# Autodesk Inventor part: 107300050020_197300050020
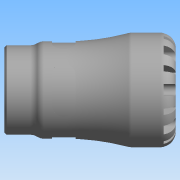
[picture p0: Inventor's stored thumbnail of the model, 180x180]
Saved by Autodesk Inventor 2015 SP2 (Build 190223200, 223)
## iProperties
Created: 2016-12
Part Number: 107300050020_197300050020
Material: Generic
Description: PLASSON FEMALE INTEGRAL BRASS THREAD 50X2" SERIES 1
Document SubType Name: Modeling
Designer: KIM
Density: 1 g/cm^3
Appearance: Default
Author: KIM
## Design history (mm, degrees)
derived "1073.ipt"
feature "Solid1::1073.ipt"
tag "TaggingFeature1"
body "Solid1"
other parameters: "d0" = 127, "d1" = 34.02, "d3" = 62.5, "d4" = 85, "d6" = 81, "d8" = 72.25, "d13" = 9, "d14" = 9, "d15" = 0, "d17" = 360 deg, "d19" = 8 deg, "d20" = 1, "d21" = 1, "d22" = 8 deg, "d24" = 0, "d26" = 360 deg, "d32" = 8.5, "d33" = 8.5, "d39" = 1.69968, "d42" = 56.656, "d43" = 66.3, "d46" = 4.16667, "d47" = 26, "d48" = 53.8232, "d50" = 6.6, "d51" = 0.85, "d54" = 17.5, "d55" = 11, "d57" = 17.64, "d58" = 0, "d68" = 360 deg, "d72" = 1, "d74" = 0, "d76" = 14.875, "E_" = 85, "H_" = 127, "l_" = 81, "G_" = 56.656, "l_2" = 26, "d9" = 11.25, "d11" = 85, "d12" = 62.5
